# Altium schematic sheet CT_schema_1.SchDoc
size 495 x 480 mm
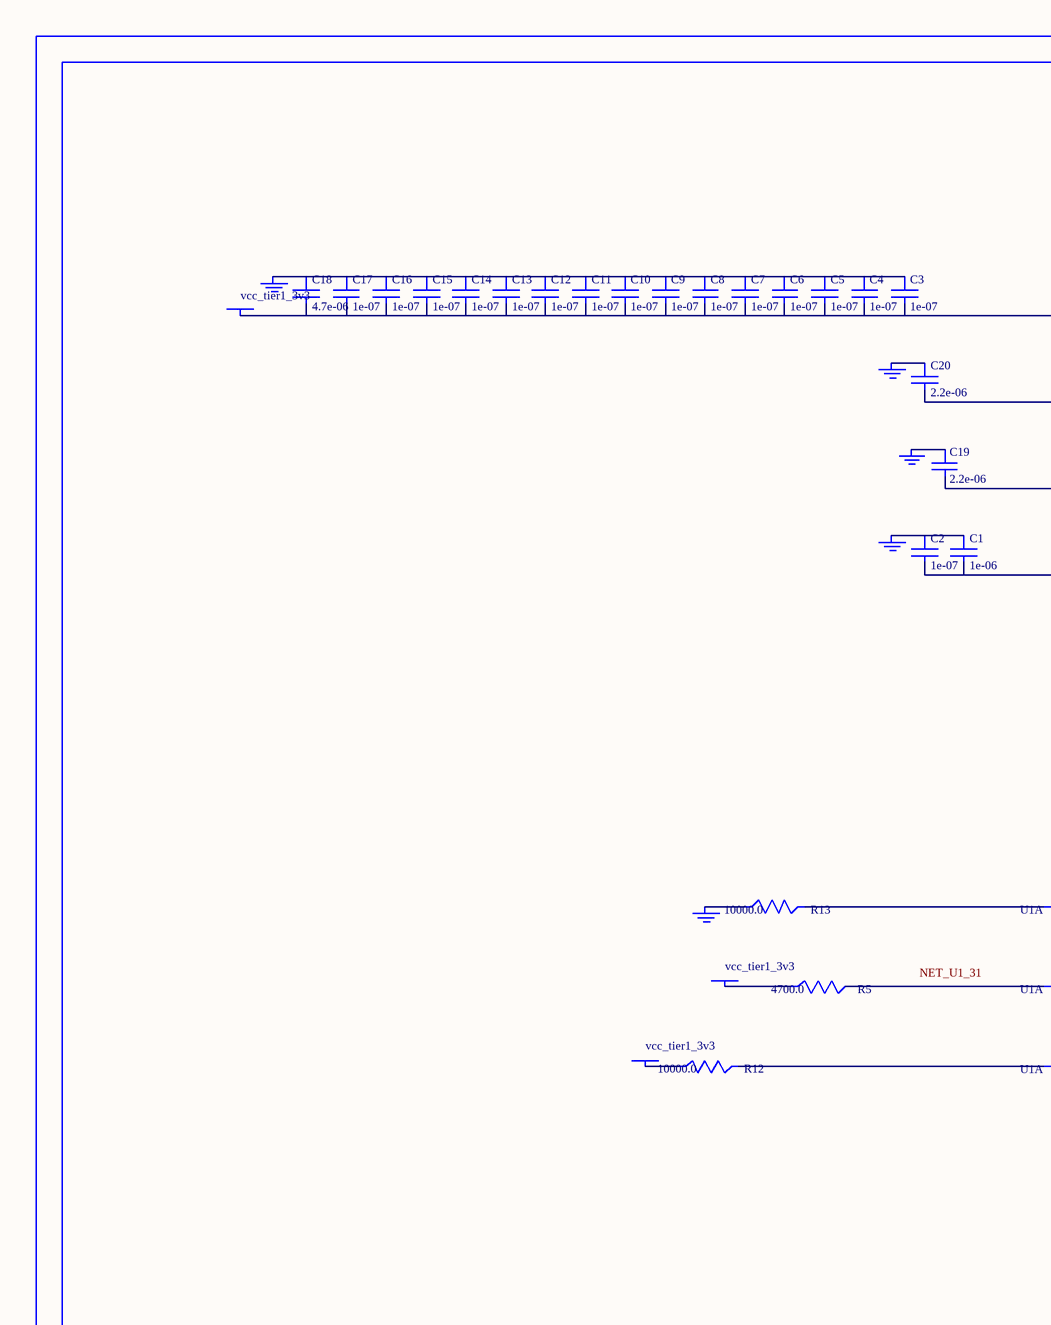
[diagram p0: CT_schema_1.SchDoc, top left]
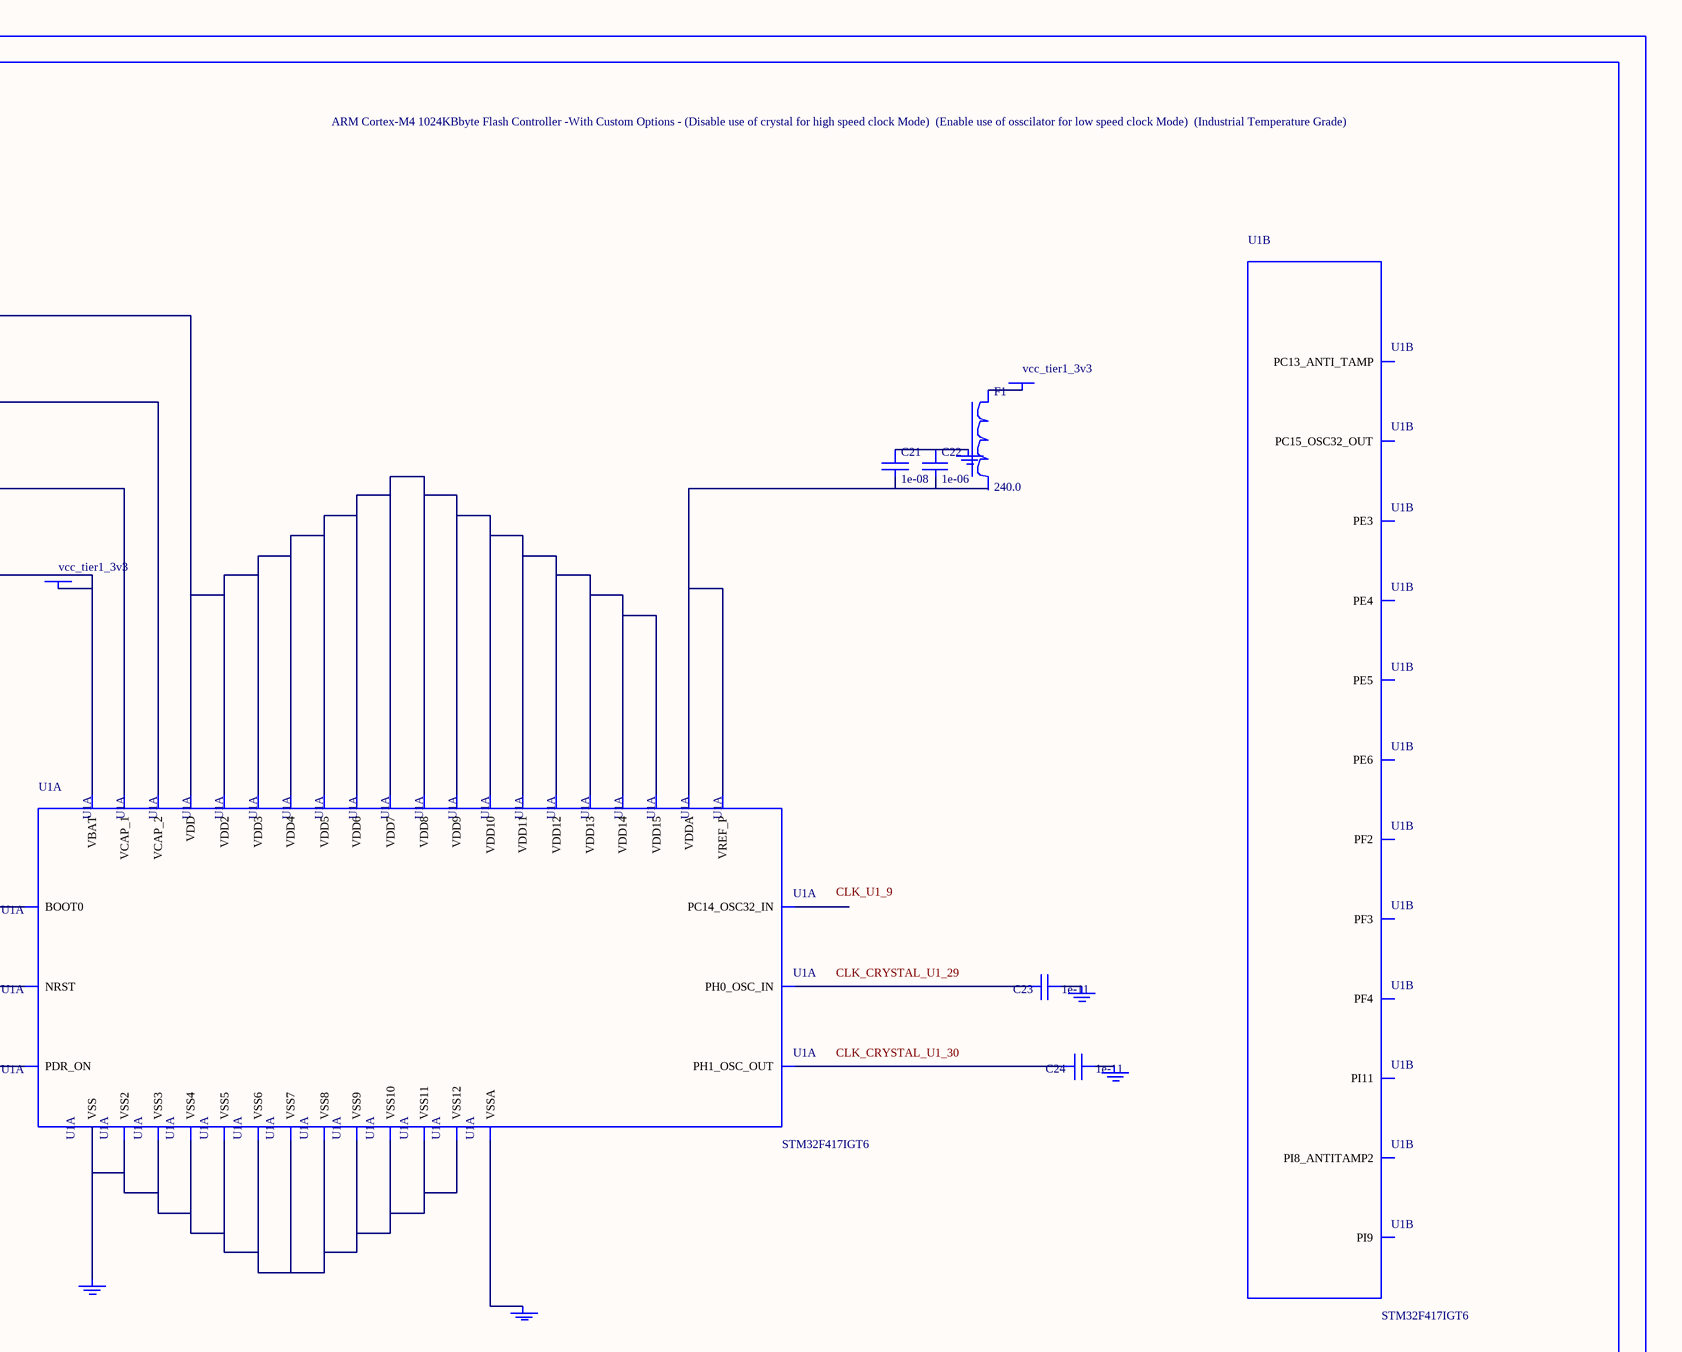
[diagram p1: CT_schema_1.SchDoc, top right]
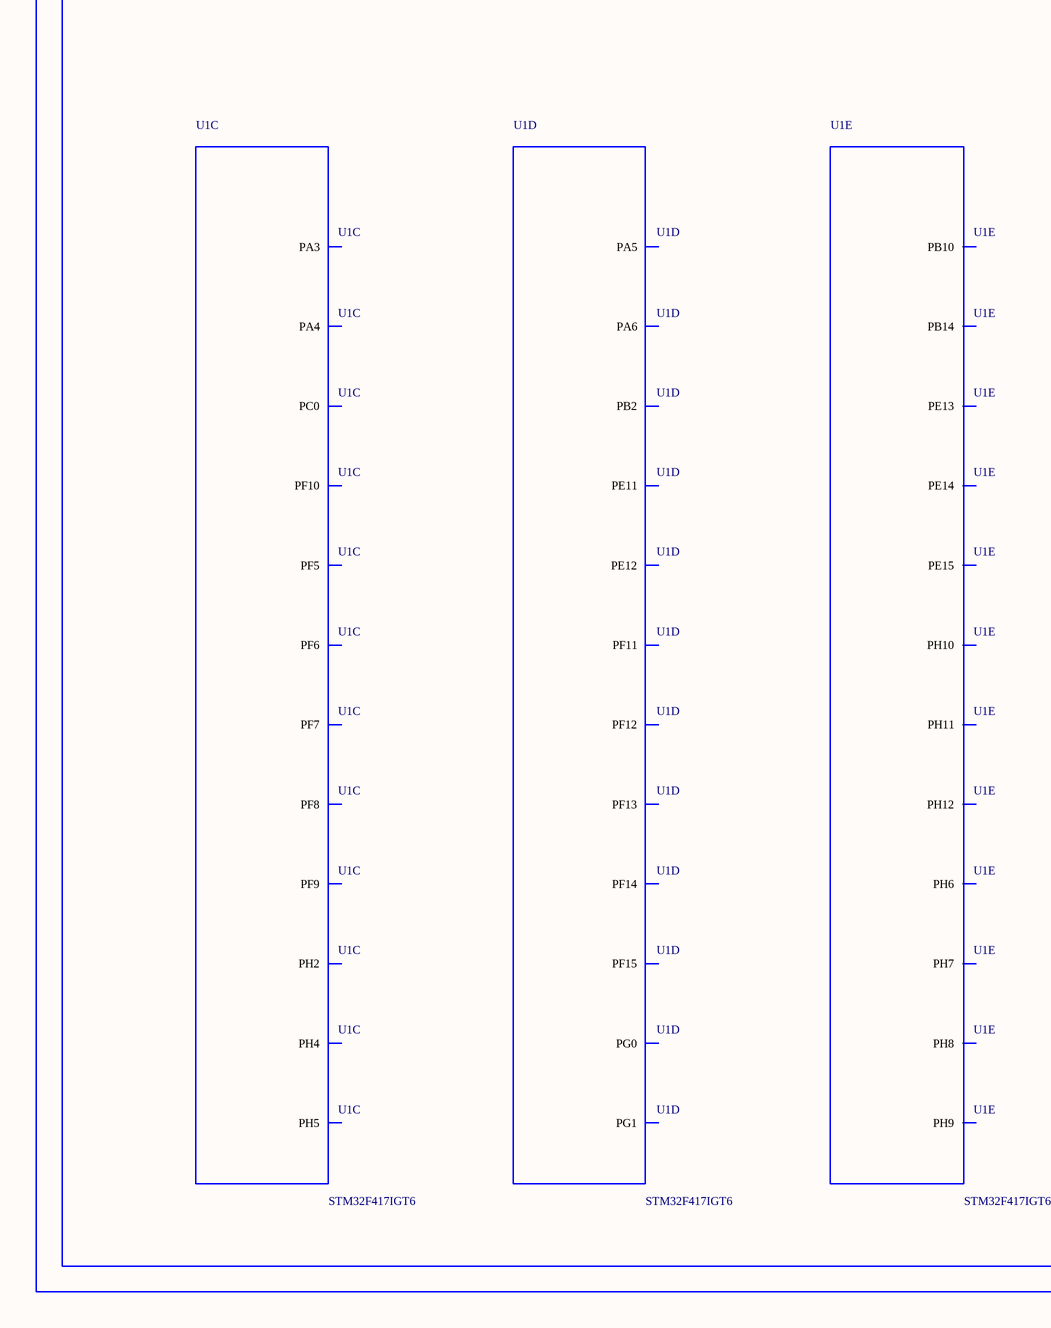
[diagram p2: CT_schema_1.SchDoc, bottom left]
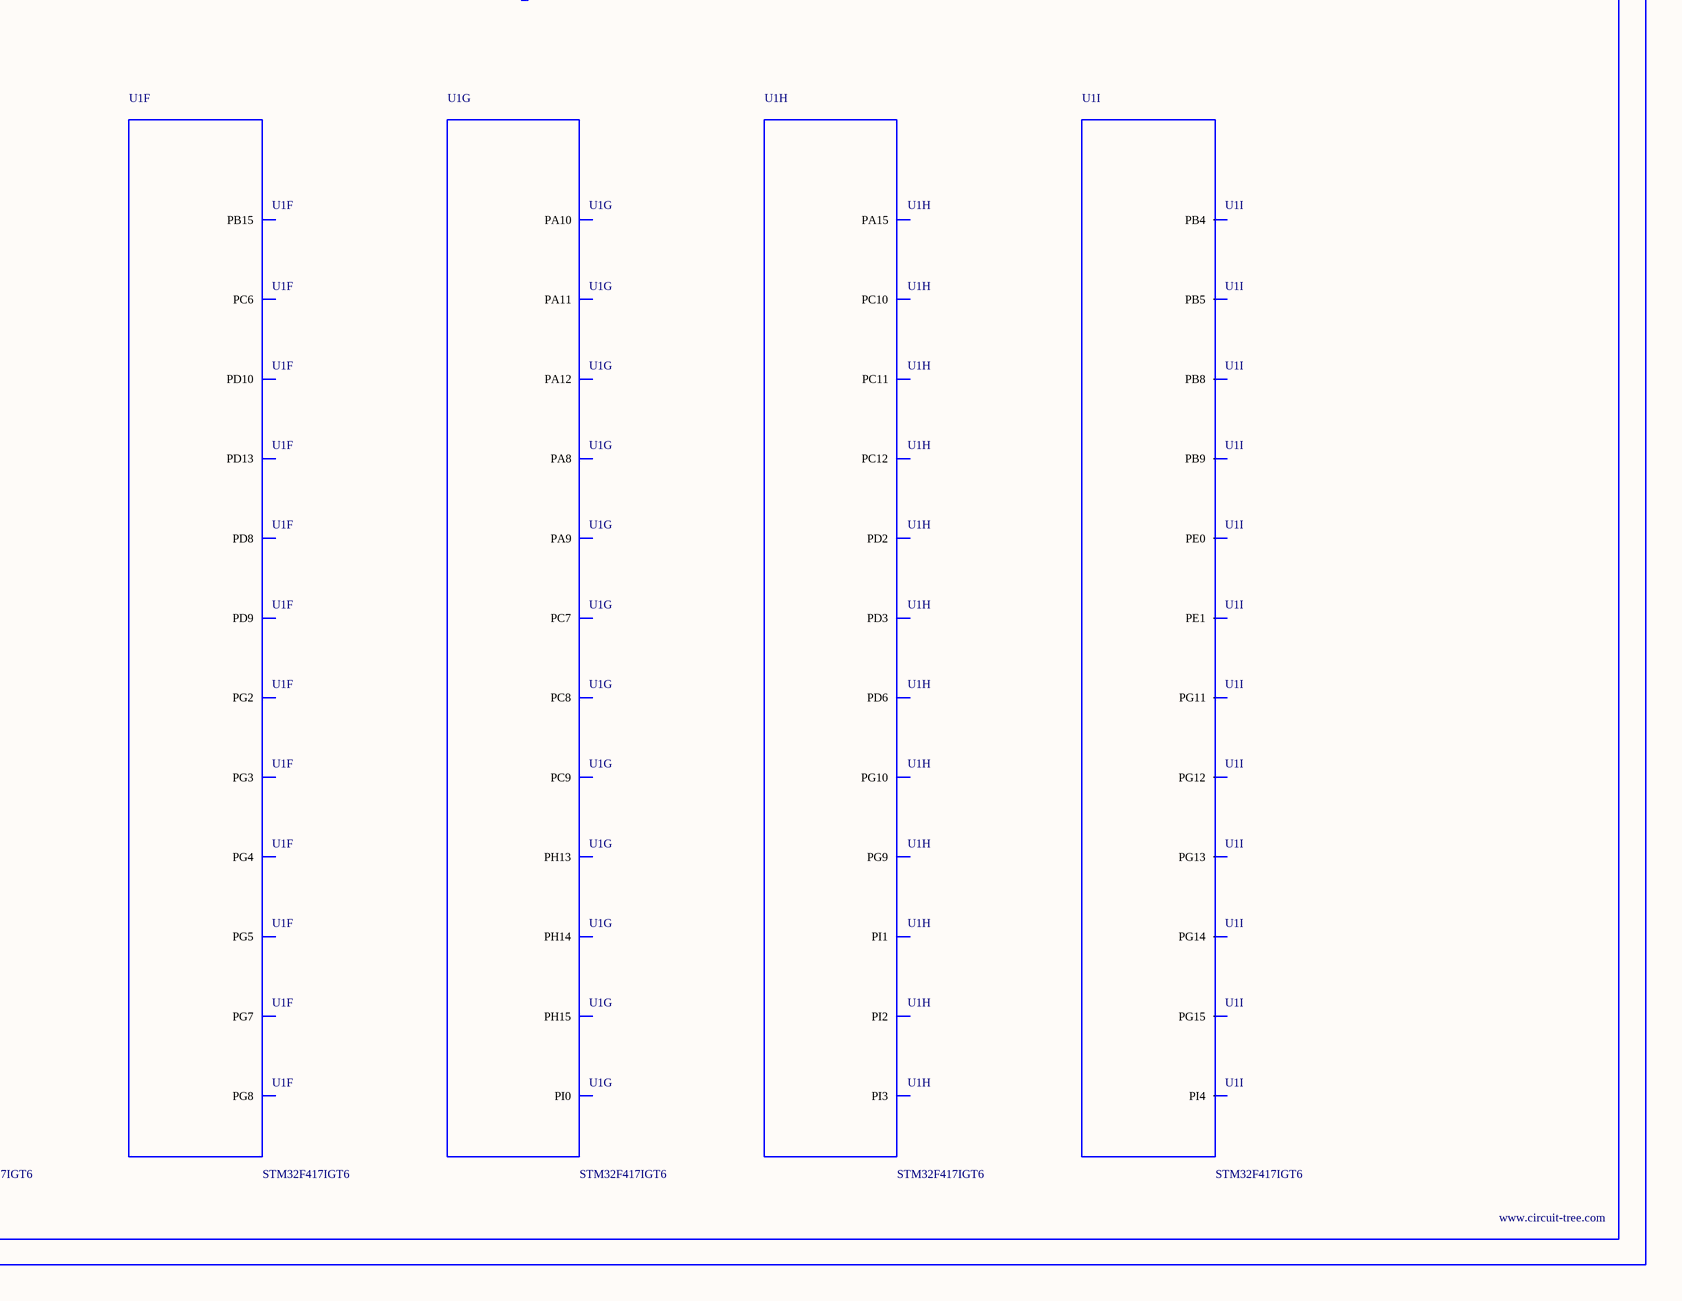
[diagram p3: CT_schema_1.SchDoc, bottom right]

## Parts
BORDER0  (no value)
C1  1e-06  [C0603]
C2  1e-07  [C0603]
C3  1e-07  [C0603]
C4  1e-07  [C0603]
C5  1e-07  [C0603]
C6  1e-07  [C0603]
C7  1e-07  [C0603]
C8  1e-07  [C0603]
C9  1e-07  [C0603]
C10  1e-07  [C0603]
C11  1e-07  [C0603]
C12  1e-07  [C0603]
C13  1e-07  [C0603]
C14  1e-07  [C0603]
C15  1e-07  [C0603]
C16  1e-07  [C0603]
C17  1e-07  [C0603]
C18  4.7e-06  [C0603]
C19  2.2e-06  [C0603]
C20  2.2e-06  [C0603]
C21  1e-08  [C0603]
C22  1e-06  [C0603]
C23  1e-11  [C0402]
C24  1e-11  [C0402]
F1  240.0  [L0603]
GND_INSTANCE_0_0  (no value)
GND_INSTANCE_0_1  (no value)
GND_INSTANCE_0_2  (no value)
GND_INSTANCE_0_3  (no value)
GND_INSTANCE_0_4  (no value)
GND_INSTANCE_0_5  (no value)
GND_INSTANCE_0_6  (no value)
GND_INSTANCE_0_7  (no value)
GND_INSTANCE_0_8  (no value)
GND_INSTANCE_0_9  (no value)
POWER_INSTANCE_0_0  vcc_tier1_3v3
POWER_INSTANCE_0_1  vcc_tier1_3v3
POWER_INSTANCE_0_2  vcc_tier1_3v3
POWER_INSTANCE_0_3  vcc_tier1_3v3
POWER_INSTANCE_0_4  vcc_tier1_3v3
R5  4700.0  [R0603]
R12  10000.0  [R0603]
R13  10000.0  [R0603]
U1  STM32F417IGT6  [LQFP176]  (parts A,B,C,D,E,F,G,H,I of 16)

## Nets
NetC1_1: C1.1 C2.1 GND_INSTANCE_0_0.0(GND)
NetC1_2: C1.2 C2.2 POWER_INSTANCE_0_0.0(PWR) U1.6(VBAT)
NetC3_1: C3.1 C4.1 C5.1 C6.1 C7.1 C8.1 C9.1 C10.1 C11.1 C12.1 C13.1 C14.1 C15.1 C16.1 C17.1 C18.1 GND_INSTANCE_0_1.0(GND)
NetC3_2: C3.2 C4.2 C5.2 C6.2 C7.2 C8.2 C9.2 C10.2 C11.2 C12.2 C13.2 C14.2 C15.2 C16.2 C17.2 C18.2 POWER_INSTANCE_0_1.0(PWR) U1.15(VDD) U1.23(VDD2) U1.36(VDD3) U1.49(VDD4) U1.62(VDD5) U1.72(VDD6) U1.82(VDD7) U1.91(VDD8) U1.103(VDD9) U1.114(VDD10) U1.127(VDD11) U1.136(VDD12) U1.149(VDD13) U1.159(VDD14) U1.172(VDD15)
NetC19_1: C19.1 GND_INSTANCE_0_6.0(GND)
NetC19_2: C19.2 U1.81(VCAP_1)
NetC20_1: C20.1 GND_INSTANCE_0_7.0(GND)
NetC20_2: C20.2 U1.125(VCAP_2)
NetC21_1: C21.1 C22.1 GND_INSTANCE_0_5.0(GND)
NetC21_2: C21.2 C22.2 U1.38(VREF_P) U1.39(VDDA)
NetC23_1: C23.1 GND_INSTANCE_0_2.0(GND)
NetC23_2: C23.2 U1.29(PH0_OSC_IN)
NetC24_1: C24.1 GND_INSTANCE_0_3.0(GND)
NetC24_2: C24.2 U1.30(PH1_OSC_OUT)
NetF1_1: F1.1 POWER_INSTANCE_0_2.0(PWR)
NetGND_INSTANCE_0_4_0: GND_INSTANCE_0_4.0(GND) U1.37(VSSA)
NetGND_INSTANCE_0_8_0: GND_INSTANCE_0_8.0(GND) R13.1
NetGND_INSTANCE_0_9_0: GND_INSTANCE_0_9.0(GND) U1.14(VSS) U1.22(VSS2) U1.48(VSS3) U1.61(VSS4) U1.71(VSS5) U1.90(VSS6) U1.102(VSS7) U1.113(VSS8) U1.126(VSS9) U1.135(VSS10) U1.148(VSS11) U1.158(VSS12)
NetPOWER_INSTANCE_0_3_0: POWER_INSTANCE_0_3.0(PWR) R12.1
NetPOWER_INSTANCE_0_4_0: POWER_INSTANCE_0_4.0(PWR) R5.1
NetR5_2: R5.2 U1.31(NRST)
NetR12_2: R12.2 U1.171(PDR_ON)
NetR13_2: R13.2 U1.166(BOOT0)

Not connected (* = marked no-connect by the designer): F1 2; U1 2(PE3) 3(PE4) 4(PE5) 5(PE6) 7(PI8_ANTITAMP2) 8(PC13_ANTI_TAMP) 9(PC14_OSC32_IN) 10(PC15_OSC32_OUT) 11(PI9) 13(PI11) 18(PF2) 19(PF3) 20(PF4) 21(PF5) 24(PF6) 25(PF7) 26(PF8) 27(PF9) 28(PF10) 32(PC0) 43(PH2) 45(PH4) 46(PH5) 47(PA3) 50(PA4) 51(PA5) 52(PA6) 58(PB2) 59(PF11) 60(PF12) 63(PF13) 64(PF14) 65(PF15) 66(PG0) 67(PG1) 74(PE11) 75(PE12) 76(PE13) 77(PE14) 78(PE15) 79(PB10) 83(PH6) 84(PH7) 85(PH8) 86(PH9) 87(PH10) 88(PH11) 89(PH12) 94(PB14) 95(PB15) 96(PD8) 97(PD9) 98(PD10) 101(PD13) 106(PG2) 107(PG3) 108(PG4) 109(PG5) 111(PG7) 112(PG8) 115(PC6) 116(PC7) 117(PC8) 118(PC9) 119(PA8) 120(PA9) 121(PA10) 122(PA11) 123(PA12) 128(PH13) 129(PH14) 130(PH15) 131(PI0) 132(PI1) 133(PI2) 134(PI3) 138(PA15) 139(PC10) 140(PC11) 141(PC12) 144(PD2) 145(PD3) 150(PD6) 152(PG9) 153(PG10) 154(PG11) 155(PG12) 156(PG13) 157(PG14) 160(PG15) 162(PB4) 163(PB5) 167(PB8) 168(PB9) 169(PE0) 170(PE1) 173(PI4)

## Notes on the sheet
- Labels drawn without touching a wire or pin: CLK_CRYSTAL_U1_29, CLK_CRYSTAL_U1_30, CLK_U1_9, NET_U1_31

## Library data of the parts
BORDER0 = BORDER_PAGE0
C1 C22 = C0603C105K3RACTU
C2-C17 = 06035C104K4Z2A
C18 = GRM188R6YA475KE15D
C19 C20 = C0603C225K8RACTU
C21 = 06035C103K4Z2A
C23 C24 = C0402C100K3GACTU
F1 = Z0603C241ASMST
GND_INSTANCE_0_0-GND_INSTANCE_0_9 = GND
POWER_INSTANCE_0_0-POWER_INSTANCE_0_4 = PWR
R5 = RC0603JR-074K7L
R12 R13 = RC0603JR-0710KL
